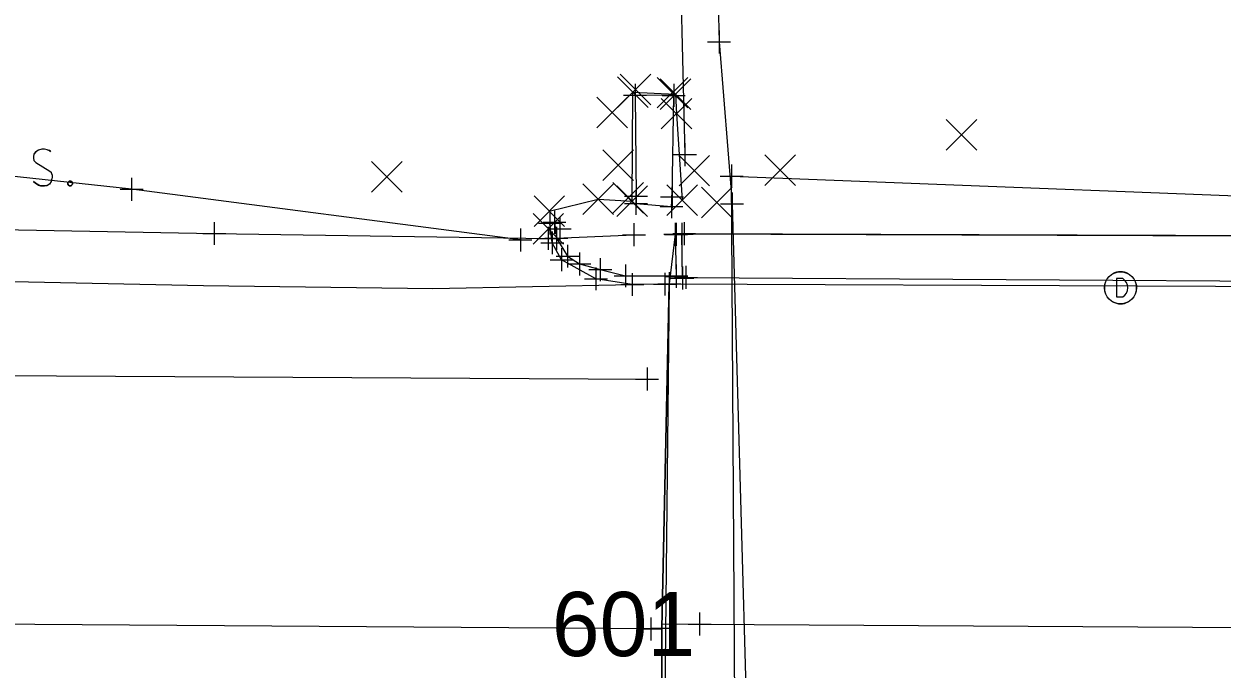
# Model space of a CAD drawing. Extents: x 146022 to 147632, y 437624 to 440659.
# Drawn here: x 146857.8 to 146910.1, y 438626.1 to 438654.2 of the extents above; entities that cross this region are included whole.
import ezdxf

# ---------------------------------------------------------------- set-up
doc = ezdxf.new("R2010")
doc.units = 0
for name, color, linetype in [('_CIVIL_CONSTRUCTION', 7, 'Continuous'), ('BR_P_Rail_Object', 7, 'Continuous'), ('Default', 7, 'Continuous'), ('DR_Channel', 7, 'Continuous'), ('DR_X_Cells', 7, 'Continuous'), ('DT_X_Triangles', 7, 'Continuous'), ('GE_P_Alignment_100_Bearings', 7, 'Continuous'), ('GE_P_Alignment_100_Cardinal_Points', 7, 'Continuous'), ('GE_P_Alignment_100_Stations', 7, 'Continuous'), ('PF_X_Ground_Line', 7, 'Continuous'), ('PV_P_Curb', 7, 'Continuous'), ('PV_P_Shoulder', 7, 'Continuous'), ('RD_P_Anchor_Assembly', 7, 'Continuous'), ('RD_P_GR_Lt_Replaced', 7, 'Continuous'), ('SC_Scratch3', 7, 'Continuous'), ('SH_Text', 7, 'Continuous'), ('SV_X_Terrain_Boundary', 7, 'Continuous'), ('UT_X_Electric', 7, 'Continuous')]:
    doc.layers.add(name, color=color, linetype=linetype)

msp = doc.modelspace()

# ---------------------------------------------------------------- linework, layer by layer
at = {"layer": '_CIVIL_CONSTRUCTION'}
for p, q in [((146883.71, 438650.556), (146885.043, 438651.891)), ((146883.71, 438651.891), (146885.043, 438650.556)), ((146883.825, 438650.666), (146885.159, 438652.001)), ((146883.825, 438652.001), (146885.159, 438650.666)), ((146885.438, 438650.535), (146886.771, 438651.87)), ((146885.438, 438651.87), (146886.771, 438650.535)), ((146885.57, 438650.464), (146886.903, 438651.799)), ((146885.57, 438651.799), (146886.903, 438650.464)), ((146882.81, 438649.668), (146884.143, 438651.003)), ((146882.81, 438651.003), (146884.143, 438649.668)), ((146885.62, 438649.617), (146886.953, 438650.952)), ((146885.62, 438650.952), (146886.953, 438649.617)), ((146898.052, 438648.693), (146899.385, 438650.028)), ((146898.052, 438650.028), (146899.385, 438648.693)), ((146883.077, 438647.366), (146884.41, 438648.701)), ((146883.077, 438648.701), (146884.41, 438647.366)), ((146886.396, 438647.131), (146887.729, 438648.466)), ((146886.396, 438648.466), (146887.729, 438647.131)), ((146890.14, 438647.154), (146891.474, 438648.489)), ((146890.14, 438648.489), (146891.474, 438647.154)), ((146872.985, 438646.867), (146874.318, 438648.202)), ((146872.985, 438648.202), (146874.318, 438646.867)), ((146882.203, 438645.895), (146883.537, 438647.23)), ((146882.203, 438647.23), (146883.537, 438645.895)), ((146883.508, 438645.949), (146884.841, 438647.284)), ((146883.508, 438647.284), (146884.841, 438645.949)), ((146883.683, 438645.798), (146885.017, 438647.133)), ((146883.683, 438647.133), (146885.017, 438645.798)), ((146885.869, 438645.844), (146887.203, 438647.179)), ((146885.869, 438647.179), (146887.203, 438645.844)), ((146887.381, 438645.738), (146888.715, 438647.073)), ((146887.381, 438647.073), (146888.715, 438645.738)), ((146880.07, 438645.365), (146881.403, 438646.7)), ((146880.07, 438646.7), (146881.403, 438645.365)), ((146880.026, 438644.597), (146881.359, 438645.932)), ((146880.026, 438645.932), (146881.359, 438644.597))]:
    msp.add_line(p, q, dxfattribs=at)
at = {"layer": 'BR_P_Rail_Object'}
msp.add_lwpolyline([(146861.305, 438682.287), (146861.802, 438673.799), (146886.471, 438672.389), (146886.371, 438659.854), (146886.653, 438648.503)], dxfattribs=at)
at = {"layer": 'DR_Channel'}
msp.add_lwpolyline([(146815.073, 438703.582), (146813.174, 438696.091), (146813.467, 438678.631), (146815.154, 438668.877), (146817.531, 438663.047), (146825.174, 438653.203), (146835.67, 438647.109), (146842.306, 438645.689), (146845.94, 438645.439), (146866.123, 438645.06), (146880.69, 438644.846), (146884.427, 438645.003)], dxfattribs=at)
at = {"layer": 'DR_X_Cells'}
for points in [[(146888.686, 438647.566), (146919.282, 438646.371), (146923.453, 438610.256)], [(146923.453, 438610.256), (146914.918, 438606.992), (146888.926, 438608.466), (146888.686, 438647.566)]]:
    msp.add_lwpolyline(points, dxfattribs=at)
at = {"layer": 'DT_X_Triangles'}
msp.add_line((146905.649, 438642.69), (146905.649, 438642.69), dxfattribs=at)
msp.add_line((146905.649, 438642.69), (146905.649, 438642.69), dxfattribs=at)
msp.add_line((146905.649, 438642.69), (146905.649, 438642.69), dxfattribs=at)
msp.add_line((146905.649, 438642.69), (146905.649, 438642.69), dxfattribs=at)
msp.add_line((146905.649, 438642.69), (146905.649, 438642.69), dxfattribs=at)
msp.add_circle((146905.649, 438642.69), 0.7, dxfattribs=at)
at = {"layer": 'GE_P_Alignment_100_Bearings'}
msp.add_line((146886.09, 438646.665), (146886.09, 438646.665), dxfattribs=at)
msp.add_lwpolyline([(146886.067, 438646.234), (146886.09, 438646.665), (146886.163, 438651.085), (146884.474, 438651.09), (146884.521, 438646.693), (146884.517, 438646.37)], close=True, dxfattribs=at)
at = {"layer": 'GE_P_Alignment_100_Cardinal_Points'}
msp.add_line((146885.895, 438643.207), (146886.272, 438643.206), dxfattribs=at)
for points in [[(146885.777, 438642.85), (146884.354, 438642.836), (146882.772, 438643.083), (146881.269, 438643.917), (146880.863, 438644.651), (146880.759, 438645.516)], [(146880.963, 438645.551), (146881.047, 438644.851), (146881.536, 438644.072), (146882.047, 438643.731), (146882.956, 438643.484), (146884.062, 438643.214), (146885.89, 438643.207)], [(146885.777, 438642.85), (146884.354, 438642.836), (146882.772, 438643.083), (146881.269, 438643.917), (146880.863, 438644.651)], [(146886.697, 438643.146), (146914.629, 438642.971), (146987.485, 438642.673), (147030.154, 438642.484), (147082.653, 438642.27), (147087.676, 438642.282), (147088.142, 438642.428), (147088.538, 438642.44)]]:
    msp.add_lwpolyline(points, dxfattribs=at)
at = {"layer": 'GE_P_Alignment_100_Stations'}
msp.add_lwpolyline([(146886.617, 438645.057), (146916.632, 438644.953), (146969.533, 438644.744), (146993.171, 438644.674), (147051.149, 438644.479), (147087.815, 438644.354), (147088.055, 438644.306), (147088.543, 438644.321)], dxfattribs=at)
at = {"layer": 'PF_X_Ground_Line'}
for p, q in [((146880.736, 438646.032), (146882.87, 438646.563)), ((146882.87, 438646.563), (146884.35, 438646.465)), ((146885.966, 438642.868), (146885.67, 438614.858))]:
    msp.add_line(p, q, dxfattribs=at)
for points in [[(146874.321, 439086.085), (146876.116, 439048.972), (146877.594, 438969.184), (146878.821, 438878.151), (146882.493, 438787.417), (146884.674, 438714.134), (146887.53, 438676.634), (146888.14, 438653.413), (146888.706, 438646.352), (146889.72, 438610.795)], [(146879.476, 438644.781), (146862.517, 438646.987), (146840.846, 438649.333), (146828.353, 438657.047), (146816.171, 438677.325), (146820.636, 438693.859), (146821.236, 438709.799)], [(146884.35, 438646.465), (146884.377, 438651.224), (146886.237, 438651.131), (146886.287, 438650.284), (146886.536, 438646.512)], [(146886.231, 438645.023), (146886.276, 438643.188)], [(146886.541, 438643.113), (146886.515, 438645.026)], [(146886.541, 438643.113), (146886.515, 438645.026)]]:
    msp.add_lwpolyline(points, dxfattribs=at)
at = {"layer": 'PV_P_Curb'}
msp.add_line((146887.294, 438628.027), (146885.658, 438628.001), dxfattribs=at)
for points in [[(146885.159, 438627.811), (146831.415, 438628.197)], [(146887.294, 438628.027), (146961.353, 438627.571), (147033.742, 438627.551), (147087.577, 438627.48)]]:
    msp.add_lwpolyline(points, dxfattribs=at)
at = {"layer": 'PV_P_Shoulder'}
for points in [[(146858.992, 438648.617), (146858.97, 438648.642), (146858.937, 438648.667), (146858.838, 438648.705), (146858.717, 438648.73), (146858.629, 438648.73), (146858.596, 438648.73), (146858.452, 438648.692), (146858.331, 438648.617), (146858.254, 438648.516), (146858.232, 438648.415), (146858.232, 438648.34), (146858.254, 438648.239), (146858.342, 438648.151), (146858.948, 438647.773), (146859.003, 438647.723), (146859.025, 438647.672), (146859.047, 438647.597), (146859.047, 438647.521), (146859.037, 438647.445), (146859.025, 438647.395), (146859.003, 438647.332), (146858.981, 438647.282), (146858.959, 438647.244), (146858.926, 438647.206), (146858.893, 438647.181), (146858.849, 438647.156), (146858.816, 438647.143), (146858.717, 438647.13), (146858.562, 438647.13), (146858.463, 438647.156), (146858.32, 438647.244), (146858.232, 438647.319)], [(146858.996, 438648.622), (146858.974, 438648.647), (146858.941, 438648.672), (146858.842, 438648.71), (146858.72, 438648.735), (146858.632, 438648.735), (146858.599, 438648.735), (146858.456, 438648.697), (146858.335, 438648.622), (146858.258, 438648.521), (146858.235, 438648.42), (146858.235, 438648.345), (146858.258, 438648.244), (146858.346, 438648.156), (146858.952, 438647.778), (146859.007, 438647.727), (146859.029, 438647.677), (146859.051, 438647.601), (146859.051, 438647.526), (146859.04, 438647.45), (146859.029, 438647.4), (146859.007, 438647.337), (146858.985, 438647.286), (146858.963, 438647.249), (146858.93, 438647.211), (146858.897, 438647.186), (146858.853, 438647.16), (146858.82, 438647.148), (146858.72, 438647.135), (146858.566, 438647.135), (146858.467, 438647.16), (146858.324, 438647.249), (146858.235, 438647.324)], [(146859.808, 438647.345), (146859.863, 438647.345), (146859.896, 438647.319), (146859.929, 438647.269), (146859.929, 438647.206), (146859.896, 438647.156), (146859.863, 438647.13), (146859.808, 438647.13), (146859.775, 438647.156), (146859.742, 438647.206), (146859.742, 438647.269), (146859.775, 438647.319), (146859.808, 438647.345)], [(146859.812, 438647.349), (146859.867, 438647.349), (146859.9, 438647.324), (146859.933, 438647.274), (146859.933, 438647.211), (146859.9, 438647.16), (146859.867, 438647.135), (146859.812, 438647.135), (146859.779, 438647.16), (146859.746, 438647.211), (146859.746, 438647.274), (146859.779, 438647.324), (146859.812, 438647.349)]]:
    msp.add_lwpolyline(points, dxfattribs=at)
at = {"layer": 'RD_P_Anchor_Assembly'}
for p, q in [((146888.14, 438653.913), (146888.14, 438652.913)), ((146887.64, 438653.413), (146888.64, 438653.413)), ((146888.14, 438653.413), (146888.14, 438653.413)), ((146884.474, 438651.59), (146884.474, 438650.59)), ((146886.163, 438651.585), (146886.163, 438650.585)), ((146883.974, 438651.09), (146884.974, 438651.09)), ((146884.474, 438651.09), (146884.474, 438651.09)), ((146885.663, 438651.085), (146886.663, 438651.085)), ((146886.163, 438651.085), (146886.163, 438651.085)), ((146886.653, 438649.003), (146886.653, 438648.003)), ((146886.153, 438648.503), (146887.153, 438648.503)), ((146886.653, 438648.503), (146886.653, 438648.503)), ((146888.686, 438648.066), (146888.686, 438647.066)), ((146862.517, 438647.487), (146862.517, 438646.487)), ((146888.186, 438647.566), (146889.186, 438647.566)), ((146888.686, 438647.566), (146888.686, 438647.566)), ((146862.017, 438646.987), (146863.017, 438646.987)), ((146862.517, 438646.987), (146862.517, 438646.987)), ((146884.517, 438646.87), (146884.517, 438645.87)), ((146884.521, 438647.193), (146884.521, 438646.193)), ((146886.09, 438647.165), (146886.09, 438646.165)), ((146888.706, 438646.852), (146888.706, 438645.852)), ((146884.017, 438646.37), (146885.017, 438646.37)), ((146884.021, 438646.693), (146885.021, 438646.693)), ((146884.517, 438646.37), (146884.517, 438646.37)), ((146884.521, 438646.693), (146884.521, 438646.693)), ((146885.59, 438646.665), (146886.59, 438646.665)), ((146886.067, 438646.734), (146886.067, 438645.734)), ((146886.09, 438646.665), (146886.09, 438646.665)), ((146888.206, 438646.352), (146889.206, 438646.352)), ((146888.706, 438646.352), (146888.706, 438646.352)), ((146880.759, 438646.016), (146880.759, 438645.016)), ((146880.963, 438646.051), (146880.963, 438645.051)), ((146881.193, 438645.761), (146881.193, 438644.761)), ((146885.567, 438646.234), (146886.567, 438646.234)), ((146886.067, 438646.234), (146886.067, 438646.234)), ((146866.123, 438645.56), (146866.123, 438644.56)), ((146879.476, 438645.281), (146879.476, 438644.281)), ((146880.259, 438645.516), (146881.259, 438645.516)), ((146880.463, 438645.551), (146881.463, 438645.551)), ((146880.69, 438645.346), (146880.69, 438644.346)), ((146880.693, 438645.261), (146881.693, 438645.261)), ((146880.759, 438645.516), (146880.759, 438645.516)), ((146880.963, 438645.551), (146880.963, 438645.551)), ((146881.047, 438645.351), (146881.047, 438644.351)), ((146881.193, 438645.261), (146881.193, 438645.261)), ((146884.427, 438645.503), (146884.427, 438644.503)), ((146886.231, 438645.523), (146886.231, 438644.523)), ((146886.265, 438645.52), (146886.265, 438644.52)), ((146886.515, 438645.526), (146886.515, 438644.526)), ((146886.515, 438645.526), (146886.515, 438644.526)), ((146886.617, 438645.557), (146886.617, 438644.557)), ((146865.623, 438645.06), (146866.623, 438645.06)), ((146866.123, 438645.06), (146866.123, 438645.06)), ((146878.976, 438644.781), (146879.976, 438644.781)), ((146879.476, 438644.781), (146879.476, 438644.781)), ((146880.19, 438644.846), (146881.19, 438644.846)), ((146880.547, 438644.851), (146881.547, 438644.851)), ((146880.69, 438644.846), (146880.69, 438644.846)), ((146880.863, 438645.151), (146880.863, 438644.151)), ((146880.863, 438645.151), (146880.863, 438644.151)), ((146881.047, 438644.851), (146881.047, 438644.851)), ((146883.927, 438645.003), (146884.927, 438645.003)), ((146884.427, 438645.003), (146884.427, 438645.003)), ((146885.731, 438645.023), (146886.731, 438645.023)), ((146885.765, 438645.02), (146886.765, 438645.02)), ((146886.015, 438645.026), (146887.015, 438645.026)), ((146886.015, 438645.026), (146887.015, 438645.026)), ((146886.117, 438645.057), (146887.117, 438645.057)), ((146886.231, 438645.023), (146886.231, 438645.023)), ((146886.265, 438645.02), (146886.265, 438645.02)), ((146886.515, 438645.026), (146886.515, 438645.026)), ((146886.515, 438645.026), (146886.515, 438645.026)), ((146886.617, 438645.057), (146886.617, 438645.057)), ((146880.363, 438644.651), (146881.363, 438644.651)), ((146880.363, 438644.651), (146881.363, 438644.651)), ((146880.863, 438644.651), (146880.863, 438644.651)), ((146880.863, 438644.651), (146880.863, 438644.651)), ((146881.269, 438644.417), (146881.269, 438643.417)), ((146881.269, 438644.417), (146881.269, 438643.417)), ((146881.536, 438644.572), (146881.536, 438643.572)), ((146882.047, 438644.231), (146882.047, 438643.231)), ((146880.769, 438643.917), (146881.769, 438643.917)), ((146880.769, 438643.917), (146881.769, 438643.917)), ((146881.036, 438644.072), (146882.036, 438644.072)), ((146881.269, 438643.917), (146881.269, 438643.917)), ((146881.269, 438643.917), (146881.269, 438643.917)), ((146881.536, 438644.072), (146881.536, 438644.072)), ((146881.547, 438643.731), (146882.547, 438643.731)), ((146882.047, 438643.731), (146882.047, 438643.731)), ((146882.956, 438643.984), (146882.956, 438642.984)), ((146884.062, 438643.714), (146884.062, 438642.714)), ((146886.272, 438643.706), (146886.272, 438642.706)), ((146886.276, 438643.688), (146886.276, 438642.688)), ((146886.276, 438643.688), (146886.276, 438642.688)), ((146882.456, 438643.484), (146883.456, 438643.484)), ((146882.772, 438643.583), (146882.772, 438642.583)), ((146882.772, 438643.583), (146882.772, 438642.583)), ((146882.956, 438643.484), (146882.956, 438643.484)), ((146883.562, 438643.214), (146884.562, 438643.214)), ((146884.062, 438643.214), (146884.062, 438643.214)), ((146884.354, 438643.336), (146884.354, 438642.336)), ((146884.354, 438643.336), (146884.354, 438642.336)), ((146885.772, 438643.206), (146886.772, 438643.206)), ((146885.776, 438643.188), (146886.776, 438643.188)), ((146885.776, 438643.188), (146886.776, 438643.188)), ((146885.777, 438643.35), (146885.777, 438642.35)), ((146885.777, 438643.35), (146885.777, 438642.35)), ((146885.966, 438643.368), (146885.966, 438642.368)), ((146886.197, 438643.146), (146887.197, 438643.146)), ((146886.272, 438643.206), (146886.272, 438643.206)), ((146886.276, 438643.188), (146886.276, 438643.188)), ((146886.276, 438643.188), (146886.276, 438643.188)), ((146886.541, 438643.613), (146886.541, 438642.613)), ((146886.541, 438643.613), (146886.541, 438642.613)), ((146886.697, 438643.646), (146886.697, 438642.646)), ((146886.697, 438643.146), (146886.697, 438643.146)), ((146882.272, 438643.083), (146883.272, 438643.083)), ((146882.272, 438643.083), (146883.272, 438643.083)), ((146882.772, 438643.083), (146882.772, 438643.083)), ((146882.772, 438643.083), (146882.772, 438643.083)), ((146883.854, 438642.836), (146884.854, 438642.836)), ((146883.854, 438642.836), (146884.854, 438642.836)), ((146884.354, 438642.836), (146884.354, 438642.836)), ((146884.354, 438642.836), (146884.354, 438642.836)), ((146885.277, 438642.85), (146886.277, 438642.85)), ((146885.277, 438642.85), (146886.277, 438642.85)), ((146885.466, 438642.868), (146886.466, 438642.868)), ((146885.777, 438642.85), (146885.777, 438642.85)), ((146885.777, 438642.85), (146885.777, 438642.85)), ((146885.966, 438642.868), (146885.966, 438642.868)), ((146886.041, 438643.113), (146887.041, 438643.113)), ((146886.041, 438643.113), (146887.041, 438643.113)), ((146886.541, 438643.113), (146886.541, 438643.113)), ((146886.541, 438643.113), (146886.541, 438643.113)), ((146885, 438639.209), (146885, 438638.209)), ((146884.5, 438638.709), (146885.5, 438638.709)), ((146885, 438638.709), (146885, 438638.709)), ((146887.294, 438628.527), (146887.294, 438627.527)), ((146885.159, 438628.311), (146885.159, 438627.311)), ((146885.649, 438628.345), (146885.649, 438627.345)), ((146886.794, 438628.027), (146887.794, 438628.027)), ((146887.294, 438628.027), (146887.294, 438628.027)), ((146884.659, 438627.811), (146885.659, 438627.811)), ((146885.149, 438627.845), (146886.149, 438627.845)), ((146885.159, 438627.811), (146885.159, 438627.811)), ((146885.649, 438627.845), (146885.649, 438627.845))]:
    msp.add_line(p, q, dxfattribs=at)
at = {"layer": 'RD_P_GR_Lt_Replaced'}
msp.add_lwpolyline([(146816.743, 438756.129), (146815.488, 438746.208), (146815.334, 438744.991), (146813.998, 438735.081), (146813.18, 438729.017), (146812.134, 438719.072), (146811.633, 438714.315), (146810.818, 438704.348), (146810.142, 438696.074), (146809.683, 438686.085), (146809.486, 438681.807), (146810.985, 438673.681), (146812.773, 438666.233), (146816.012, 438661.204), (146822.963, 438654.015), (146824.249, 438652.685), (146828.099, 438649), (146836.066, 438643.896), (146845.523, 438643.414), (146855.515, 438643.008), (146855.927, 438642.991), (146865.653, 438642.787), (146875.652, 438642.66), (146884.354, 438642.836)], dxfattribs=at)
at = {"layer": 'SC_Scratch3'}
msp.add_line((146841.687, 438638.943), (146885, 438638.709), dxfattribs=at)
at = {"layer": 'SH_Text'}
msp.add_lwpolyline([(146885.966, 438642.868), (146926.812, 438642.691), (146985.277, 438642.496), (147039.933, 438642.254), (147088.536, 438642.067), (147088.54, 438627.583), (147088.397, 438614.111), (147046.407, 438614.279), (146992.08, 438614.464), (146931.328, 438614.71), (146885.67, 438614.858), (146885.649, 438627.845)], close=True, dxfattribs=at)
at = {"layer": 'SV_X_Terrain_Boundary'}
msp.add_lwpolyline([(146885.67, 438614.858), (146885.705, 438612.644), (147088.417, 438611.938), (147088.276, 438614.389), (147088.54, 438627.583), (147088.536, 438642.067), (147088.543, 438644.321), (147051.149, 438644.479), (146993.171, 438644.674), (146969.533, 438644.744), (146886.231, 438645.023), (146885.966, 438642.868), (146885.966, 438642.868), (146885.649, 438627.845)], close=True, dxfattribs=at)
at = {"layer": 'UT_X_Electric'}
msp.add_lwpolyline([(146905.749, 438643.09), (146905.469, 438643.09), (146905.469, 438642.29), (146905.749, 438642.29)], dxfattribs=at)
for centre, radius, start, end in [((146905.649, 438642.69), 0.7, 60.0184, 120.0157), ((146905.649, 438642.69), 0.7, 150.0184, 209.9816), ((146905.494, 438642.69), 0.474, 302.5148, 57.4852), ((146905.649, 438642.69), 0.7, 330.0184, 29.9816), ((146905.649, 438642.69), 0.7, 239.9843, 299.9816)]:
    msp.add_arc(centre, radius, start, end, dxfattribs=at)

# ---------------------------------------------------------------- texts
at = {"layer": 'Default'}
msp.add_text('601', height=2.8, dxfattribs=at).set_placement((146880.848, 438626.627))

doc.saveas('drawing.dxf')
